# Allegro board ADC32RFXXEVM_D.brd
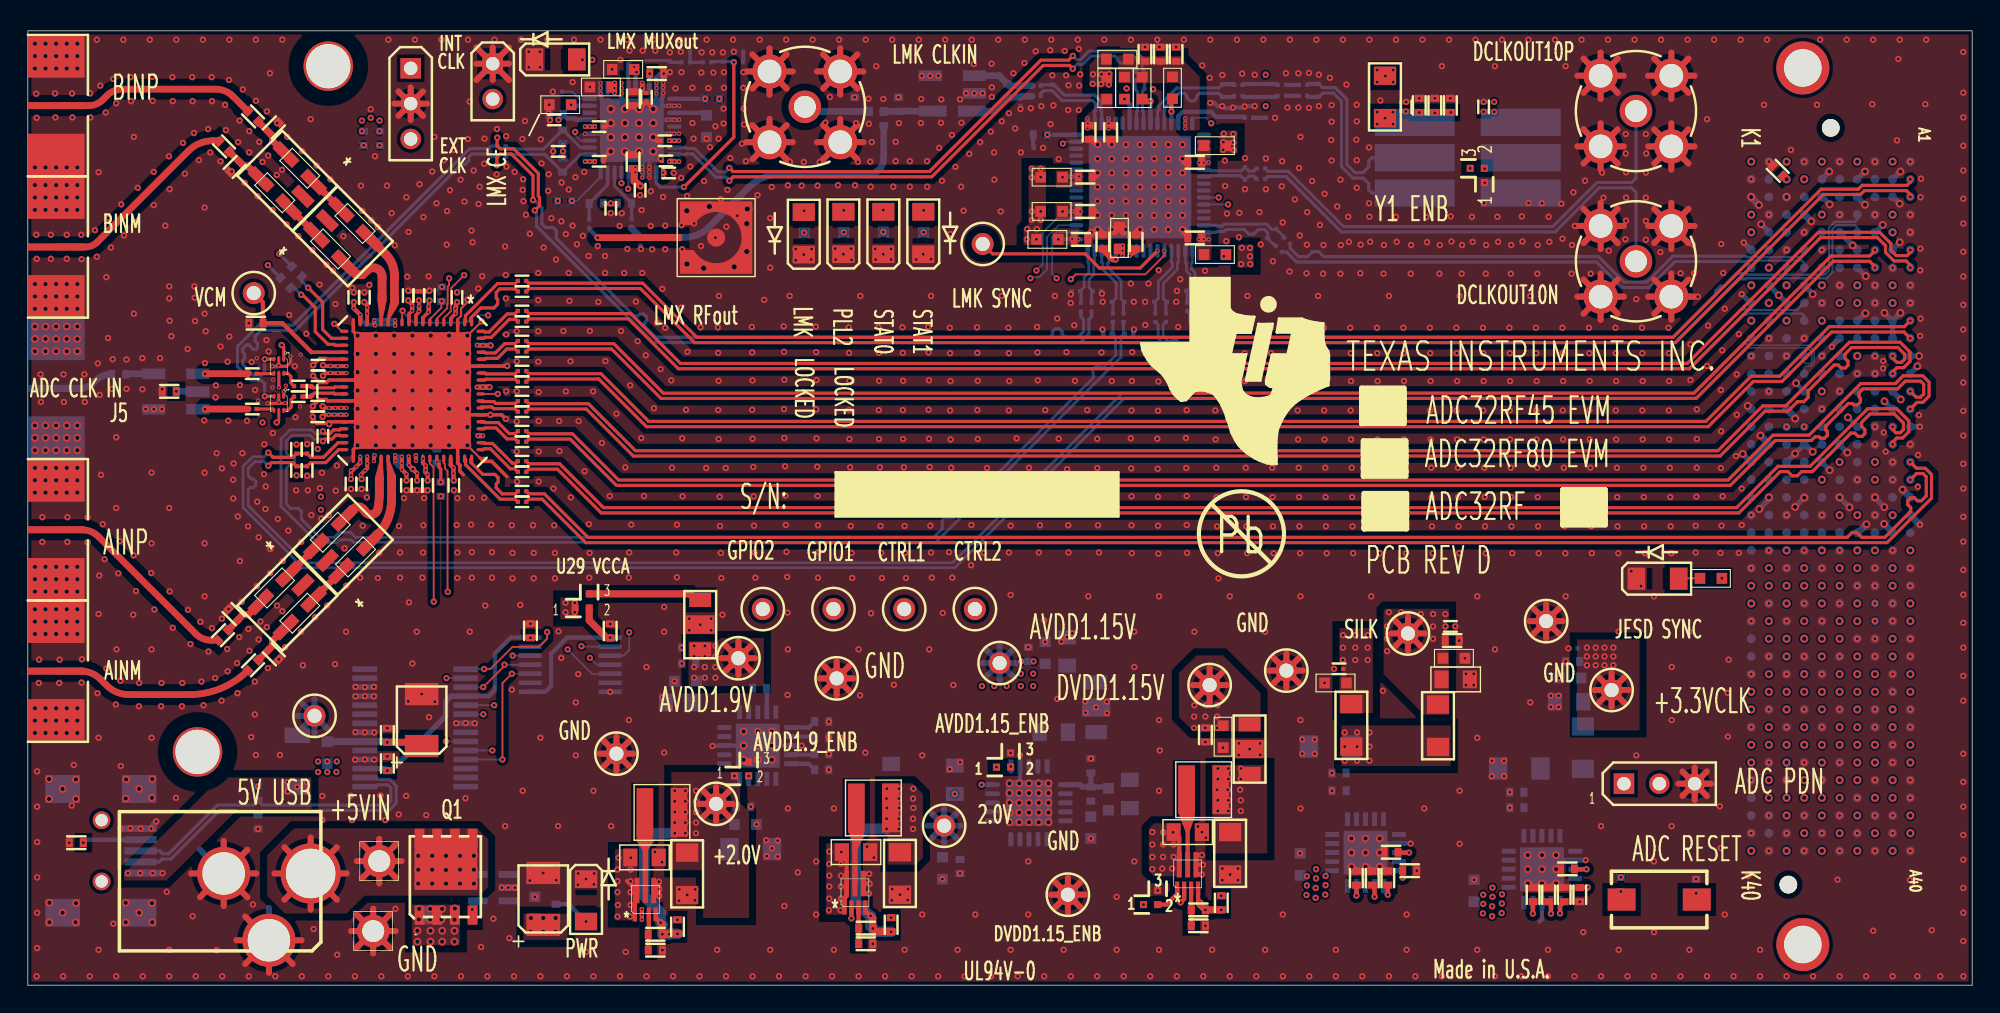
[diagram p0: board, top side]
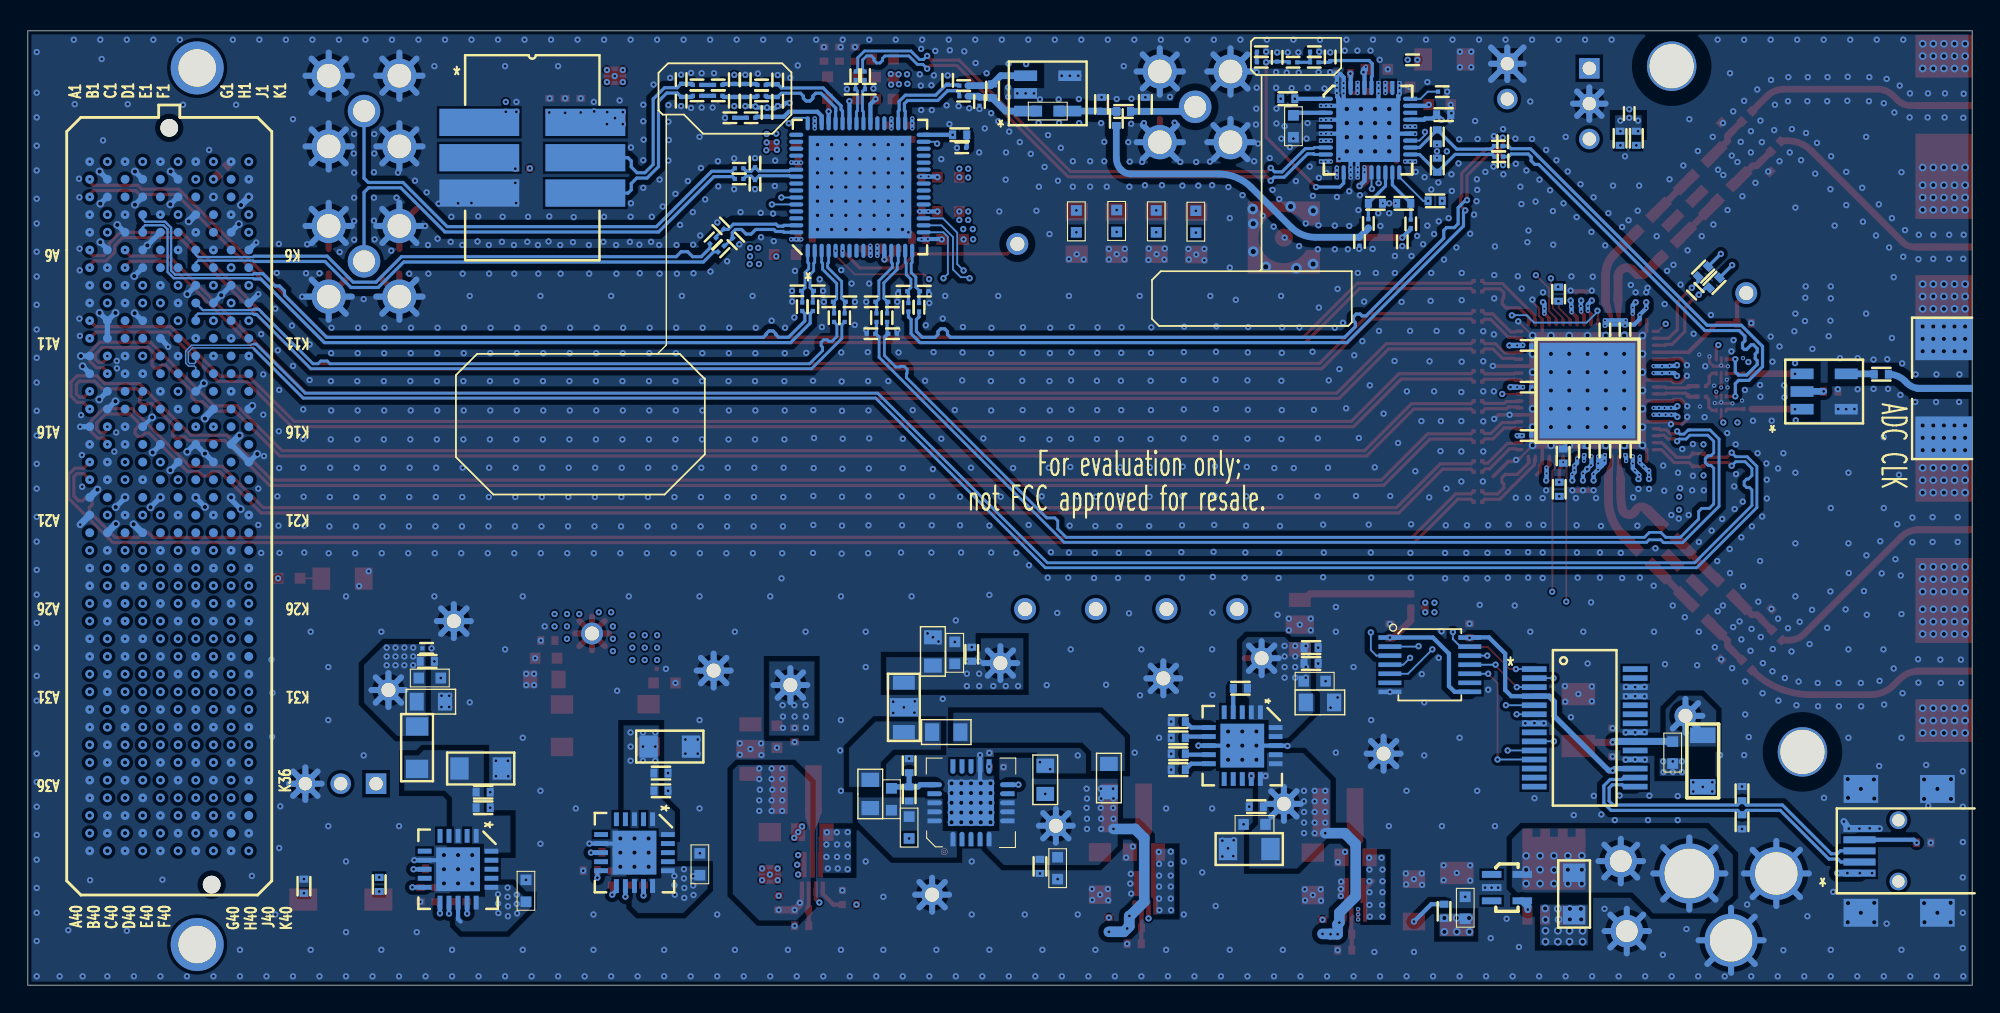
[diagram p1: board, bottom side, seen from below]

Outline 139.7 x 68.58 mm; copper layers: TOP, L2_GND, L3_PWR, L4_SIG, L5_GND, L6_PWR, L7_GND, BOTTOM. Coordinates in mm from the lower left corner of the outline.
Outline path: 0,68.58 0,0 139.7,0 139.7,68.58 0,68.58

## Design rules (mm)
net group CLK: nets CLKM CLKP
net group CLK_LAO: nets CLK_LAO_0M CLK_LAO_0P
net group CLKIN1: nets CLKIN1_N CLKIN1_P
net group DA0: nets DA0M DA0P
net group DA1: nets DA1M DA1P
net group DA2: nets DA2M DA2P
net group DA3: nets DA3M DA3P
net group DB0: nets DB0M DB0P
net group DB1: nets DB1M DB1P
net group DB2: nets DB2M DB2P
net group DB3: nets DB3M DB3P
net group DIFFPAIR9: nets GTXCLKM GTXCLKP
net group DP1: nets N19886018 N19886020
net group DP2: nets CLKLA_0M CLKLA_0P
net group DP3: nets N20235277 N20235286
net group DP4: nets N20015888 N20015984
net group DP5: nets SYSREF+ SYSREF-
net group DP6: nets AINM AINP
net group DP7: nets BINM BINP
net group DP8: nets LMX_OSCM LMX_OSCP
net group DP9: nets DA0_M DA0_P
net group DP10: nets DA1_M DA1_P
net group DP11: nets DA2_M DA2_P
net group DP12: nets DA3_M DA3_P
net group DP13: nets DB0_M DB0_P
net group DP14: nets DB1_M DB1_P
net group DP15: nets DB2_M DB2_P
net group DP16: nets DB3_M DB3_P
net group DP17: nets JESD_SYSREFM JESD_SYSREFP
net group DP18: nets N19879103 N19879149
net group DP19: nets LMX_CLKM LMX_CLKP
net group FPGA_JESD_CLK: nets FPGA_JESD_CLKM FPGA_JESD_CLKP
net group FPGA_JESD_SYSREF: nets FPGA_JESD_SYSREFM FPGA_JESD_SYSREFP
net group OSC: nets OSCN OSCP
net group OSCIN: nets OSCINN OSCINP
net group OSCOUT: nets OSCOUTN OSCOUTP
net group SYNCB: nets SYNCBM SYNCBP
net group SYSREF: nets SYSREFM SYSREFP
net group Y2: nets Y2_N Y2_P

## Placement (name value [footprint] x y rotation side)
C1  .1uF  [0603]  21.73 32.55 45 top
C6  .1uF  [0603]  23.55 30.77 45 top
C7  .1uF  [0603]  23.51 54.74 315 top
C8  .1uF  [0201]  76.43 48.72 270 bottom
C9  .1uF  [0201]  75.67 48.72 270 bottom
C12  .1uF  [0603]  21.75 52.9 315 top
C13  .1uF  [0201]  35.51 41.21 0 top
C14  .1uF  [0201]  35.51 41.97 0 top
C15  .1uF  [0201]  35.51 39.05 0 top
C16  .1uF  [0201]  35.51 39.81 0 top
C17  .1uF  [0201]  35.51 36.89 0 top
C18  .1uF  [0201]  35.51 37.66 0 top
C19  .1uF  [0201]  35.51 34.73 0 top
C20  .1uF  [0201]  35.51 35.5 0 top
C21  .1uF  [0201]  35.51 44.13 0 top
C22  .1uF  [0201]  35.51 43.37 0 top
C23  .1uF  [0201]  35.51 46.29 0 top
C24  .1uF  [0201]  35.51 45.53 0 top
C26  .1uF  [0201]  35.51 48.45 0 top
C27  .1uF  [0201]  35.51 47.69 0 top
C28  .01uF  [0402]  6.53 43.9 0 bottom
C30  .1uF  [0201]  35.51 50.61 0 top
C31  .1uF  [0201]  35.51 49.85 0 top
C33  .1uF  [0402]  10.16 42.67 180 top
C37  .1uF  [0201]  28.09 49.56 90 top
C38  .1uF  [0201]  26.39 47.09 270 bottom
C39  .1uF  [0201]  24.94 47.12 270 bottom
C40  .1uF  [0201]  23.42 49.43 90 top
C41  .1uF  [0201]  20.85 43.79 180 top
C42  .1uF  [0201]  20.83 41.61 180 top
C43  .1uF  [0201]  23.22 36.02 270 top
C44  .1uF  [0201]  24.92 38.38 90 bottom
C45  .1uF  [0201]  26.39 38.38 90 bottom
C46  .1uF  [0201]  27.2 35.92 270 top
C47  .1uF  [0201]  27.86 38.38 90 bottom
C48  .1uF  [0201]  27.33 49.56 90 top
C49  .1uF  [0201]  24.18 49.43 90 top
C50  .01uF  [0201]  20.85 44.55 180 top
C51  .01uF  [0201]  20.83 40.84 180 top
C52  .1uF  [0201]  23.98 36.02 270 top
C53  .1uF  [0201]  27.97 35.92 270 top
C54  .1uF  [0201]  30.84 49.43 90 top
C55  .1uF  [0201]  28.85 49.56 90 top
C56  .1uF  [0201]  28.73 35.92 270 top
C57  .1uF  [0201]  30.61 35.92 270 top
C58  .1uF  [0201]  31.98 39.5 180 bottom
C59  .1uF  [0201]  31.98 42.98 180 bottom
C60  .1uF  [0201]  31.98 45.97 180 bottom
C61  .1uF  [0402]  16.38 47.57 180 top
C67  .1uF  [0201]  84.06 48.75 270 bottom
C68  .1uF  [0201]  104.6 63.12 90 top
C69  .1uF  [0201]  83.3 48.75 270 bottom
C70  .68uF  [0402]  72.75 61.11 180 bottom
C71  3900pF  [0201]  87.73 62.33 0 bottom
C72  47pF  [0201]  86.59 62.71 90 bottom
C73  .01uF  [0201]  72.47 63.88 0 bottom
C74  .01uF  [0201]  72.47 64.64 0 bottom
C75  .1uF  [0201]  73.61 65.02 270 bottom
C77  .1uF  [0201]  99.03 63.12 270 top
C78  100pF  [0402]  99.97 63.22 270 top
C79  2200pF  [0402]  101.09 63.22 270 top
C80  10pF  [0402]  102.21 63.22 270 top
C81  .1uF  [0201]  90.09 64.69 180 bottom
C82  .1uF  [0201]  86.98 64.69 180 bottom
C83  .1uF  [0201]  85.82 65.05 270 bottom
C84  .1uF  [0201]  90.09 63.91 180 bottom
C85  .1uF  [0201]  86.98 63.9 180 bottom
C86  12pF  [0201]  85.82 63.52 90 bottom
C87  1uF  [0402]  76.25 61.29 90 top
C88  .1uF  [0402]  79.63 53.42 270 top
C89  0.01uF  [0402]  77.8 61.29 90 top
C90  1uF  [0402]  75.67 53.59 180 top
C91  1uF  [0402]  75.97 55.6 180 top
C92  1uF  [0402]  75.97 58.06 180 top
C93  1uF  [0402]  80.26 66.9 270 top
C94  .1uF  [0402]  81.38 66.9 270 top
C95  0.01uF  [0402]  82.5 66.9 270 top
C96  .1uF  [0402]  77.24 53.42 90 top
C97  10uF  [0603]  78.44 53.7 90 top
C98  1uF  [0402]  83.85 59.13 0 top
C99  1uF  [0402]  83.85 53.7 0 top
C101  4.7uF  [TANT_B]  28.3 19.05 90 top
C102  .1uF  [0402]  25.83 17.96 90 top
C103  47pF  [0402]  16.54 11.73 270 bottom
C104  47pF  [0402]  16.54 13.77 90 bottom
C105  .1uF  [0402]  25.83 15.93 90 top
C121  10uF  [0805]  59.51 9.56 0 top
C122  1uF  [0402]  66.98 8.53 270 bottom
C126  2.2uF  [0603]  65.71 8.41 270 bottom
C156  10uF  [0603]  103.91 6.78 90 bottom
C157  .1uF  [0402]  106.98 12.75 180 bottom
C158  1uF  [0402]  106.98 13.87 180 bottom
C159  47uF  [1206]  107.16 15.57 180 bottom
C160  33uF  [0805]  110.74 20.37 180 bottom
C161  10uF  [0603]  110.82 22.07 180 bottom
C162  .01uF  [0201]  111.05 24.21 180 bottom
C163  .1uF  [0402]  111 23.27 180 bottom
C166  1uF  [0402]  108.15 6.5 90 top
C170  .1uF  [0201]  88.6 58.7 0 bottom
C171  .1uF  [0201]  88.6 57.94 0 bottom
C172  47uF  [TANT_B]  37.03 6.2 90 top
C173  10uF  [0603]  36.42 5.56 90 bottom
C183  10uF  [0805]  44.31 9.18 0 top
C184  22uF  [1206]  47.37 8 270 top
C185  33uF  [0805]  46.86 20.32 180 bottom
C186  10uF  [0603]  47.24 21.84 180 bottom
C187  1uF  [0402]  47.5 23.11 180 bottom
C188  .1uF  [0402]  47.5 24.26 180 bottom
C189  47uF  [1206]  51.94 9.78 0 bottom
C190  10uF  [0603]  51.56 11.56 0 bottom
C191  1uF  [0402]  51.44 12.83 0 bottom
C193  .47uF  [0603]  77.65 13.36 90 bottom
C194  33uF  [0805]  74.67 23.98 90 bottom
C195  10uF  [0603]  73.1 23.88 90 bottom
C196  1uF  [0402]  71.88 23.78 90 bottom
C197  10uF  [0603]  76.38 11.33 270 bottom
C198  4.7uF  [0805]  66.6 14.76 90 bottom
C203  10uF  [0805]  83.34 11 0 top
C204  22uF  [1206]  86.39 9.47 270 top
C368  .1uF  [0402]  41.84 25.45 90 top
C369  .1uF  [0402]  36.11 25.47 270 top
C372  .1uF  [0201]  16.13 43.94 0 top
C373  .1uF  [0201]  16.13 41.4 0 top
C376  22uF  [1206]  62.66 8.03 270 top
C377  10uF  [0603]  85.88 17.86 270 top
C378  1uF  [0402]  84.61 17.98 270 top
C379  10uF  [0603]  93.95 21.72 180 top
C380  .01uF  [0201]  94.21 22.73 180 top
C381  10uF  [0603]  102.46 23.5 0 top
C382  .1uF  [0402]  102.34 24.77 0 top
C383  .01uF  [0201]  102.21 25.78 0 top
C384  33uF  [0805]  102.59 21.97 0 top
C385  47uF  [1206]  93.57 17.14 180 bottom
C386  10uF  [0603]  91.41 8.69 90 bottom
C387  1uF  [0402]  95.45 7.7 90 top
C388  .1uF  [0402]  94.21 13.97 180 bottom
C389  1uF  [0402]  94.21 15.24 180 bottom
C390  .1uF  [0201]  41.05 61.7 180 top
C391  .1uF  [0201]  45.85 59.23 0 top
C392  .1uF  [0201]  45.77 60.68 180 top
C393  .1uF  [0201]  46.05 58.37 0 top
C394  .047uF  [0201]  51.08 66.32 0 bottom
C395  560pF  [0201]  49.94 66.67 90 bottom
C396  .1uF  [0201]  43.99 57.12 270 top
C397  .1uF  [0201]  41.05 59.21 0 top
C398  1uF  [0402]  43.48 59.18 270 top
C399  .1uF  [0201]  37.82 62.18 180 top
C400  1uF  [0402]  37.97 62.56 0 bottom
C401  .1uF  [0201]  44.45 63.8 270 top
C402  1uF  [0402]  43.51 63.7 90 top
C403  10uF  [0603]  48.77 61.72 90 bottom
C404  1uF  [0402]  45.19 65.51 180 top
C405  10uF  [0603]  38.25 63.27 0 top
C406  10uF  [0603]  42.77 65.81 0 top
C407  10uF  [0603]  41.17 64.54 0 top
C408  100pF  [0201]  38.1 59.92 180 top
C409  100pF  [0201]  34.04 60.3 180 bottom
C410  100pF  [0201]  34.01 59.54 180 bottom
C411  100pF  [0201]  41.88 55.83 270 top
C412  100pF  [0201]  43.38 54.74 270 bottom
C413  100pF  [0201]  40.34 54.71 270 bottom
C414  .1uF  [0402]  14.02 25.15 45 top
C415  .1uF  [0402]  16.18 22.99 45 top
C416  .1uF  [0402]  16.18 62.43 315 top
C417  .1uF  [0402]  14.1 60.27 315 top
C418  .1uF  [0201]  79.58 65.35 90 bottom
C419  .1uF  [0201]  80.21 65.35 90 bottom
C420  6800pF  [0201]  47.27 67.08 180 bottom
C421  6800pF  [0201]  46.13 66.7 90 bottom
C424  .1uF  [0402]  14.78 26.67 315 top
C425  .1uF  [0402]  17.68 23.77 135 top
C426  .1uF  [0402]  17.68 61.65 225 top
C427  .1uF  [0402]  14.86 58.8 45 top
C428  .1uF  [0201]  24.64 62.64 90 bottom
C429  .1uF  [0201]  19.43 43.05 0 top
C430  .1uF  [0201]  19.43 42.29 0 top
C431  .1uF  [0201]  33.73 60.6 90 bottom
C432  .1uF  [0201]  33.71 59.23 270 bottom
D1  LED GREEN  [LED_1206]  61.47 54.05 270 top
D2  LED GREEN  [LED_1206]  64.34 54.05 270 top
D3  LED GREEN  [LED_1206]  55.75 54.03 270 top
D4  LED GREEN  [LED_1206]  58.6 54.05 270 top
D5  LED GREEN  [LED_1206]  117.09 29.21 180 top
D6  LED GREEN  [LED_1206]  40.11 6.1 90 top
D7  LED GREEN  [LED_1206]  37.92 66.52 180 top
F1  FUSE 10A 63V FAST  [1206]  28.6 6.55 270 bottom
FB1  120 OHM @ 100MHz  [1206]  97.51 63.83 90 top
FB2  120  [0603]  77.52 64.47 270 top
FB3  120  [0603]  73.25 53.59 0 top
FB4  120  [0603]  73.56 55.6 0 top
FB5  120  [0603]  73.56 58.06 0 top
FB6  120  [0603]  78.28 66.55 0 top
FB7  120  [0603]  78.79 64.47 270 top
FB8  120  [0603]  80.06 64.47 270 top
FB9  120  [0603]  82.25 64.49 270 top
FB10  120  [0603]  85.29 60.33 180 top
FB11  120  [0603]  85.29 52.5 180 top
FB12  1K OHM @ 100MHz  [1806]  19.35 16.1 270 bottom
FB16  120 OHM @ 100MHz  [1206]  111.73 17.07 90 bottom
FB17  27uF  [1206_BEAD_NFM31P]  76.76 19.96 90 bottom
FB19  27uF  [1206_BEAD_NFM31P]  87.78 16.97 90 top
FB20  27uF  [1206_BEAD_NFM31P]  48.31 25.91 90 top
FB21  120 OHM @ 100MHz  [1206]  95.1 18.67 90 top
FB22  120 OHM @ 100MHz  [1206]  101.32 18.64 90 top
HS1  COPPER PIN FIN HEAT SINK  [HEATSINK_270X270]  27.64 42.72 180 bottom
J1  SMA, JACK, END LAUNCH  [SMA_SMEL_DUAL_PSF-S01_250X215]  0 32.73 90 top
J2  SMA, JACK, END LAUNCH  [SMA_SMEL_DUAL_PSF-S01_250X215]  0 22.57 90 top
J3  SMA, JACK, END LAUNCH  [SMA_SMEL_DUAL_PSF-S01_250X215]  0 63.21 90 top
J4  SMA, JACK, END LAUNCH  [SMA_SMEL_DUAL_PSF-S01_250X215]  0 53.05 90 top
J5  CONN, SMA, JACK, 50 OHM, EDGE MNT  [SMA_SMEL_DUAL_PSF-S01_250X215]  0 42.89 270 bottom
J7  SMA_THVT_REC  [SMA_THVT_312X312]  55.83 63.12 0 top
J10  CON, SMVT, HS, FIELD ARRAY, 400POS, MALE  [CON_SMVT_40X10_SEAM_MTG]  129.54 34.42 90 bottom
J11  CONN, USB MINI AB, SMT  [CON_SMRT_USBMNE20_F]  4.65 9.65 0 bottom
J13  SMA_THVT_REC  [SMA_THVT_312X312]  115.54 62.81 0 top
J14  SMA_THVT_REC  [SMA_THVT_312X312]  115.54 52.02 0 top
J15  CONN, JACK, PWR, MINI, R/A, TH  [CON_RAPC722_JACK_THVT_3]  17.2 8.03 270 top
J16  SMP_PCB_SMT  [SMP_B120]  49.45 53.72 270 top
JP1  HDR, THVT, 3POS  [HDR_THVT_1X3_100_M]  114.68 14.48 90 top
JP2  HEADER_1x2_100_430L  [HDR_THVT_1X2_100_M]  33.4 66.22 0 top
JP3  HDR, THVT, 3POS  [HDR_THVT_1X3_100_M]  27.51 65.89 0 top
L1  .47uH  [IND_SM_XFL4015]  45.56 12.41 0 top
L2  .47uH  [IND_SM_XFL4015]  60.75 12.74 0 top
L3  .47uH  [IND_SM_XFL4015]  84.48 14.05 0 top
MT1  STANDOFF, FEMALE, 4-40 X 1 3/16", AL  [MFG125_PLATED]  21.59 66.04 0 top
MT2  STANDOFF, FEMALE, 4-40 X 1 3/16", AL  [MFG125_PLATED]  12.19 16.76 0 top
NOREF  -  []  98.35 -28.6 0 top
NOREF#2  -  []  0 68.58 0 top
NOREF#3  -  []  480.29 162.18 0 top
NOREF#4  -  []  -3.84 37.72 0 top
NOREF#5  -  []  227.97 11.43 0 top
NOREF#6  -  []  12.7 0 90 top
NOREF#7  -  []  86.59 -25.65 0 top
NOREF#8  -  []  85.17 31.17 0 top
NOREF#9  -  []  -109.98 325.27 0 top
NOREF#10  -  []  -120.68 -149.22 0 top
NOREF#11  -  []  712.19 113.13 0 top
NOREF#12  -  []  101.9 3.91 0 top
NOREF#13  -  []  130.94 -11.73 0 top
NOREF#14  -  []  85.72 -4.45 180 bottom
Q1  CSD18532Q5  [SON_Q5B_8]  30.05 7.8 90 top
R1  0  [0603]  17.73 28.54 45 top
R11  0  [0603]  19.54 26.73 45 top
R13  0  [0603]  19.54 58.71 315 top
R23  0  [0603]  17.74 56.95 315 top
R26  100  [0201]  20.42 42.68 90 top
R29  100  [0201]  21.2 39.44 90 top
R31  0  [0402]  29.67 35.64 90 bottom
R32  10K  [0402]  29.39 38.02 90 bottom
R33  1K  [0402]  114.45 7.24 270 bottom
R34  1K  [0402]  29.72 49.66 270 bottom
R35  10K  [0402]  119.86 7.11 90 bottom
R40  100  [0201]  19.89 49.86 45 bottom
R47  39K  [0201]  72.59 60.17 0 bottom
R48  0  [0201]  81.77 47.97 270 bottom
R49  0  [0201]  81.01 47.97 270 bottom
R50  240  [0201]  80.63 49.11 180 bottom
R51  240  [0201]  82.15 49.11 0 bottom
R52  240  [0201]  82.92 49.9 180 bottom
R53  240  [0201]  84.44 49.9 0 bottom
R54  620  [0201]  89.26 62.33 0 bottom
R55  49.9  [0201]  71.32 63.5 270 bottom
R56  0  [0603]  66.42 62.81 0 bottom
R57  18  [0402]  60.98 62.79 0 bottom
R58  292  [0402]  59.4 63.29 90 bottom
R59  292  [0402]  62.55 63.29 90 bottom
R60  100  [0402]  70.38 64.26 90 bottom
R63  120  [0201]  76.82 49.87 0 bottom
R64  120  [0201]  75.3 49.87 180 bottom
R65  100  [0201]  78.73 47.97 270 bottom
R66  100  [0201]  77.96 47.97 270 bottom
R67  200  [0201]  79.11 49.11 0 bottom
R68  200  [0201]  77.58 49.11 180 bottom
R69  100  [0201]  77.57 46.81 180 bottom
R70  100  [0201]  79.12 46.81 0 bottom
R71  130  [0201]  88.94 65.07 270 bottom
R72  100  [0201]  91.62 64.69 180 bottom
R73  82  [0201]  92.76 65.07 90 bottom
R74  49.9  [0201]  88.15 65.07 90 bottom
R75  0  [0201]  90.47 53.49 315 bottom
R76  130  [0201]  88.94 63.52 90 bottom
R77  240  [0201]  89.91 54.56 45 bottom
R78  240  [0201]  88.83 53.48 225 bottom
R79  0  [0201]  89.89 52.91 315 bottom
R80  100  [0201]  91.62 63.91 180 bottom
R81  82  [0201]  92.76 63.53 270 bottom
R82  49.9  [0201]  88.15 63.52 270 bottom
R84  750  [0603]  61.47 54.91 270 bottom
R85  750  [0603]  64.36 54.89 270 bottom
R86  750  [0603]  55.78 54.86 270 bottom
R87  750  [0603]  58.62 54.89 270 bottom
R88  750  [0603]  120.93 29.24 0 top
R89  0  [0402]  125.73 58.52 135 top
R95  0  [0603]  21.51 16.71 90 bottom
R96  0  [0402]  3.48 10.24 0 top
R124  0  [0402]  109.27 6.5 270 top
R125  0  [0402]  110.39 6.5 270 top
R126  0  [0402]  111.51 6.5 90 top
R127  0  [0402]  110.62 8.36 0 top
R132  287K  [0402]  45.09 3.66 180 top
R133  1K  [0402]  37.95 5.31 90 bottom
R134  162K  [0402]  45.09 2.51 0 top
R136  1M  [0402]  46.68 4.19 90 top
R137  36.5K  [0402]  52.58 21.34 0 bottom
R138  0  [0402]  57.04 18.94 180 bottom
R139  0  [0402]  57.04 17.77 180 bottom
R140  0  [0402]  57.04 16.63 180 bottom
R141  0  [0402]  57.04 15.49 180 bottom
R143  2.4K  [0402]  76.38 13.74 90 bottom
R145  4.75K  [0402]  76.38 15.77 90 bottom
R146  82K  [0402]  84.1 5.41 180 top
R147  162K  [0402]  84.1 4.27 0 top
R148  1M  [0402]  85.75 5.92 90 top
R151  240  [0201]  87.45 57.56 270 bottom
R152  240  [0201]  87.45 59.08 90 bottom
R153  1M  [0402]  62.03 4.34 90 top
R154  124K  [0402]  60.21 4.1 180 top
R155  162K  [0402]  60.21 2.97 0 top
R157  0  [0805]  62.03 14.88 270 bottom
R158  0  [0805]  79.17 13.74 270 bottom
R159  0  [0805]  73.71 18.19 180 bottom
R164  0  [0402]  18.52 50.47 315 bottom
R165  0  [0402]  19.33 51.28 315 bottom
R166  182  [0201]  19.3 36.98 90 top
R167  182  [0201]  19.3 38.51 270 top
R168  68  [0201]  20.07 36.98 270 top
R169  68  [0201]  20.07 38.51 90 top
R170  0  [0402]  96.6 7.7 270 top
R171  0  [0402]  97.94 9.55 0 top
R172  0  [0402]  97.71 7.7 270 top
R173  0  [0402]  99.29 8.23 180 top
R174  150  [0201]  51.08 67.08 180 bottom
R175  49.9  [0402]  38.43 60.96 270 bottom
R176  49.9  [0402]  38.43 58.93 90 bottom
R177  49.9  [0402]  42.88 56.18 180 bottom
R178  49.9  [0402]  40.84 56.18 0 bottom
R179  680  [0201]  38.07 64.21 0 bottom
R180  240  [0201]  80.54 64.39 0 bottom
R181  240  [0201]  79.25 64.39 180 bottom
R182  0  [0201]  48.79 66.32 180 bottom
R183  12  [0201]  47.27 66.32 180 bottom
R184  0  [0402]  38.58 56.36 180 bottom
R185  680  [0201]  40.21 66.5 0 bottom
R186  12k  [0402]  49.17 63.7 0 bottom
R187  49.9  [0201]  40.94 53.42 90 bottom
R188  10K  [0402]  24.13 60.86 270 bottom
R189  10K  [0402]  25.3 60.86 270 bottom
R191  0  [0402]  61.49 62.28 270 bottom
R192  49.9  [0201]  44.02 53.44 90 bottom
SJP1  SOLDER JUMPER, 0402  [SMD_JUMPER_L_0402]  104.65 58.19 90 top
SJP2  SOLDER JUMPER, 0402  [SMD_JUMPER_L_0402]  51.28 15.04 0 top
SJP3  SOLDER JUMPER, 0402  [SMD_JUMPER_L_0402]  70.1 15.67 0 top
SJP4  SOLDER JUMPER, 0402  [SMD_JUMPER_L_0402]  80.67 5.79 0 top
SJP5  SOLDER JUMPER, 0402  [SMD_JUMPER_L_0402]  39.83 27.1 0 top
SW1  SWITCH, SMT, PUSHBUTTON  [SW_SMVT_SPST_EVQPJX_2]  117.21 6.15 0 top
T1  ETC1-1-13  [TFMR_5_150X150_50]  18.64 27.63 45 top
T2  ETC1-1-13  [TFMR_5_150X150_50]  22.63 31.65 225 top
T3  ETC1-1-13  [TFMR_5_150X150_50]  18.64 57.81 315 top
T4  ETC1-1-13  [TFMR_5_150X150_50]  22.63 53.82 135 top
T5  ETC1-1-13  [TFMR_5_150X150_50]  10.63 42.66 0 bottom
T6  TC1-1-13M+  [TFMR_5_150X150_50]  66.42 64.08 0 bottom
TP2  RED  [TP_THVT_060_RND]  16.23 49.73 0 top
TP3  YELLOW  [TP_THVT_060_RND]  57.89 27.03 0 top
TP4  RED  [TP_THVT_060_RND]  20.6 19.35 0 top
TP7  YELLOW  [TP_THVT_060_RND]  52.81 27.03 0 top
TP12  RED  [TP_THVT_060_RND]  113.79 21.21 0 top
TP17  Testloop_Red  [TESTPOINT_62DIA]  25.25 8.92 0 top
TP18  Testloop_Black  [TESTPOINT_62DIA]  24.82 3.89 0 top
TP19  BLK  [TP_THVT_060_RND]  109.09 26.16 0 top
TP20  RED  [TP_THVT_060_RND]  51.05 23.5 0 top
TP21  BLK  [TP_THVT_060_RND]  58.12 22.05 0 top
TP22  RED  [TP_THVT_060_RND]  69.82 23.14 90 top
TP25  YELLOW  [TP_THVT_060_RND]  68.61 53.26 0 top
TP26  RED  [TP_THVT_060_RND]  49.45 13.03 0 top
TP27  BLK  [TP_THVT_060_RND]  42.29 16.64 0 top
TP28  RED  [TP_THVT_060_RND]  65.84 11.46 0 top
TP29  BLK  [TP_THVT_060_RND]  74.73 6.5 0 top
TP30  RED  [TP_THVT_060_RND]  84.91 21.56 0 top
TP31  BLK  [TP_THVT_060_RND]  90.42 22.61 0 top
TP32  YELLOW  [TP_THVT_060_RND]  62.97 27.03 0 top
TP33  YELLOW  [TP_THVT_060_RND]  68.05 27.03 0 top
TP34  RED  [TP_THVT_060_RND]  99.16 25.27 0 top
U1  ADC32RF4X_72QFN  [QFN_72_10MMX10MM_0P50MM_PWRPAD]  27.64 42.74 270 top
U3  LMK04828  [QFN_64_360X360_0P50MM_PWRPAD]  79.91 57.35 90 bottom
U5  FT245RL  [SSOP_28_413X220_26]  27.84 18.49 180 bottom
U11  TPS62085  [QFN_RLT_7]  59.43 6.64 90 top
U12  TPS7A4700  [QFN_20_199X199_0P65MM]  108.79 8.33 270 bottom
U14  TPS62085  [QFN_RLT_7]  44.37 6.14 90 top
U15  TPS2400  [DBV5]  33.43 7.01 180 bottom
U16  TPS7A7200  [QFN_20_199X199_0P65MM]  52.44 17.21 270 bottom
U17  TPS74201/QFN20  [QFN20_RGW_P65PITCH]  71.93 13.11 90 bottom
U18  TPS62085  [QFN_RLT_7]  83.33 8 90 top
U29  TXB0104  [TSSOP14]  38.97 23.03 180 bottom
U30  LMX2582_LM2592  [QFN40_RTA_RTB_RHA]  43.41 61.44 180 bottom
U31  TPS7A4700  [QFN_20_199X199_0P65MM]  96.11 9.53 270 bottom
U32  MASW_009444  [PDFN_6_P35MM]  18.03 44.48 270 top
U33  MASW_009444  [PDFN_6_P35MM]  18.03 41.81 270 top
Y1  122.88MHz  [VCXO_6_CUSTOM]  103.45 59.46 180 bottom

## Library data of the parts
C1 C6 C7 C12 C414-C417 C424-C427 = CAP_0603_0.1uF_H: tolerance: 10%
C8 C9 C67 C69 C83 C87-C96 C98 C99 C170 C171 C368 C369 C390-C393 C396 C397 C399 C401 C418 C419 = CAPACITOR_NP_1: tolerance: 10%
C13-C24 C26 C27 C30 C31 = CAP_0201_0.1uF: tolerance: 10%
C28 C72 = CAP NP_0: tolerance: 5%
C33 C157 C163 C188 C382 C388 = CAP0603: tolerance: 10%
C37-C49 C52-C61 C372 C373 C428-C432 = CAP0402_0: tolerance: 10%
C50 C51 = CAP0402_0: tolerance: +/-10%
C68 C70 C71 C82 C85 C102 C105 C122 C158 C166 C191 C387 C389 C394 C395 C398 C400 C402 C404 C420 C421 = CAP NP_0: tolerance: 10%
C73 C74 = CAP_0402_0.01uF_H: tolerance: 10%
C75 = CAP_0402_0.1uF: tolerance: 10%
C77 C81 C84 = CAP_0402_0.1uF_H: tolerance: 10%
C78 C408-C413 = CAP_0603_100pF_H
C79 = CAP_0402_2200pF_H
C80 = CAP_0402_10pF_H
C86 = CAPACITOR_NP_1: tolerance: 2%
C97 = CAP NP_2: tolerance: 10%
C101 = CAP_TANT_B_4.7uF_10V
C103 C104 = CAP0603: tolerance: 1%
C121 C156 C173 C183 C187 C190 C196 C197 C203 C378 C386 C403 C405-C407 = CAP NP_1: tolerance: 10%
C126 = CAP_0603_2.2uF
C159 C189 C385 = CAP NP_0: tolerance: 20%
C160 C185 C186 C194 C195 C377 C384 = CAP0201: tolerance: 20%
C161 C379 C381 = CAP0201: tolerance: 10%
C162 C380 C383 = CAP0402_0: tolerance: 10V
C172 = CAP POL-B: tolerance: 10%
C184 C204 C376 = CAP: tolerance: 10%
C193 C198 = CAP_0603_.47uF
D1-D5 D7 = LED
D6 = LED_GREEN_1206
F1 = FUSE_0
FB1-FB12 FB16 FB21 FB22 = FERRITE_BEAD_0402_H
FB17 FB19 FB20 = BEAD_NFM31P
HS1 = HEATSINK_270x270
J1-J5 = SMA-END_PLUG_ROUND
J7 J13 J14 = SMA-THVT_142-0701-201_REC
J10 = CON_SMVT_40X10_ASP-134487-01
J11 = USB_MINI_AB_MNE20-5G5P10
J15 = CONN JACK PWR
J16 = SMP_PLUG_SMT
JP1 JP3 SJP1-SJP5 = SMD_JUMPER_1x3
JP2 = HDR_2x1_100
L1-L3 = CHOKE
MT1 MT2 = MOUNTING_HOLE
Q1 = CSD18532Q5B
R1 R11 R13 R23 = Res_0603_Zero_H_DNI
R26 R29 = Res_0201_200_H: tolerance: 1%
R31 = Res_0402_Zero_DNI
R32 R33 R35 R47 R54 R174 R188 R189 = R_1: tolerance: 1%
R34 = RES0603: tolerance: 1%
R40 = Res_0201_H: tolerance: 1%
R48 R49 R65 R66 R75 R79 R157-R159 R182 = Res_0402_Zero_H_DNI
R50-R53 R63 R64 R67 R68 R77 R78 R151 R152 R180 R181 = Res_0402_249
R55 R175-R179 R185 R187 R192 = Res_0402_49.9: tolerance: 1%
R56 R95 = Res_0603_Zero_DNI
R57 R183 R186 = Res_0402_18
R58 R59 = Res_0402_270
R60 R69 R70 = Res_0603_100
R71 R73 R74 R76 R81 R82 = RESISTOR_0: tolerance: 1%
R72 R80 = Res_0402_100_H
R84-R88 = RESISTOR_0
R89 = Res_0402_Zero
R96 R164 R165 R184 R191 = R
R124-R127 R138-R141 R170-R173 = R: tolerance: 5%
R132 R146 R154 = Res_0603_Zero_H
R133 = Res_0402_1k: tolerance: 1%
R134 R136 R147 R148 R153 R155 = R: tolerance: 1%
R137 = Res_0402_Zero_H
R143 = Res_0603_12.4k
R145 = Res_0603_10k
R166-R169 = Res_0402_49.9
SW1 = SPST_EVQ-PJ
T1-T5 = BALUN_ETC1-1-13
T6 = TFMR_5_TC1-1-13M+
TP2 TP4 = TESTPOINT_RED
TP3 TP7 TP12 TP20 TP22 TP25 TP32-TP34 = TESTPOINT_BLUE
TP17 TP18 = TESTLOOP_BLACK
TP19 TP21 TP27 TP29 TP31 = TESTPOINT_BLK
TP26 TP28 TP30 = TESTLOOP_RED
U1 = ADC32RF4X_72QFN
U3 = LMK04828
U5 = FT245RL
U11 U14 U18 = TPS62085/62086/62087
U12 U31 = TPS7A4700
U15 = TPS2400
U16 = TPS7A7300
U17 = TPS74201/QFN20
U29 = TXS0104E: Tolerance: ***; User Part Number: ***
U30 = LMX2582_LM2592
U32 U33 = RF_SWITCH_MASW_009444
Y1 = OSC_SM_6_TCO-2100-SERIES_2

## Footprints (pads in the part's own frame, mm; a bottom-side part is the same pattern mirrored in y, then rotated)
0201
  rect 0.305x0.305 smd: 1(-0.305,0) 2(0.305,0)
0402
  rect 0.508x0.635 smd: 1(-0.508,0) 2(0.508,0)
0603
  rect 0.762x0.787 smd: 1(-0.787,0) 2(0.787,0)
0805
  rect 1.016x1.27 smd: 1(-1.016,0) 2(1.016,0)
1206
  rect 1.321x1.6 smd: 1(-1.524,0) 2(1.524,0)
1206_BEAD_NFM31P
  rect 1.016x1.575 smd: 1(-1.778,0) 3(1.778,0)
  rect 1.321x2.032 smd: 2(0,0)
1806
  rect 1.118x1.829 smd: 1(-1.854,0) 2(1.854,0)
CON_RAPC722_JACK_THVT_3
  round 4.318 hole 3.556: 1(0,3.124)
  round 3.81 hole 3.048: 2(0,-3.124) 3(4.801,0.127)
CON_SMRT_USBMNE20_F
  round 1.27 hole 0.889 unplated: (0.65,-2.2) (0.65,2.2)
  rect 2.311x0.508 smd: 1(3.45,1.6) 2(3.45,0.8) 3(3.45,0) 4(3.45,-0.8) 5(3.45,-1.6)
  rect 2.489x2.007 smd: 6(-2.15,-4.45) 7(3.35,-4.45) 8(3.35,4.45) 9(-2.15,4.45)
CON_SMVT_40X10_SEAM_MTG
  round 3.81 hole 2.692: (-31.496,-2.007) (31.496,-2.007)
  round 1.27 hole 1.27 unplated: (-27.191,-3.048) (27.191,0)
  round 0.635 smd: A1(24.765,5.715) A2(23.495,5.715) A3(22.225,5.715) A4(20.955,5.715) A5(19.685,5.715) A6(18.415,5.715) A7(17.145,5.715) A8(15.875,5.715) A9(14.605,5.715) A10(13.335,5.715) A11(12.065,5.715) A12(10.795,5.715) A13(9.525,5.715) A14(8.255,5.715) A15(6.985,5.715) A16(5.715,5.715) A17(4.445,5.715) A18(3.175,5.715) A19(1.905,5.715) A20(0.635,5.715) A21(-0.635,5.715) A22(-1.905,5.715) A23(-3.175,5.715) A24(-4.445,5.715) A25(-5.715,5.715) A26(-6.985,5.715) A27(-8.255,5.715) A28(-9.525,5.715) A29(-10.795,5.715) A30(-12.065,5.715) A31(-13.335,5.715) A32(-14.605,5.715) A33(-15.875,5.715) A34(-17.145,5.715) A35(-18.415,5.715) A36(-19.685,5.715) A37(-20.955,5.715) A38(-22.225,5.715) A39(-23.495,5.715) A40(-24.765,5.715) B1(24.765,4.445) B2(23.495,4.445) B3(22.225,4.445) B4(20.955,4.445) B5(19.685,4.445) B6(18.415,4.445) B7(17.145,4.445) B8(15.875,4.445) B9(14.605,4.445) B10(13.335,4.445) B11(12.065,4.445) B12(10.795,4.445) B13(9.525,4.445) B14(8.255,4.445) B15(6.985,4.445) B16(5.715,4.445) B17(4.445,4.445) B18(3.175,4.445) B19(1.905,4.445) B20(0.635,4.445) B21(-0.635,4.445) B22(-1.905,4.445) B23(-3.175,4.445) B24(-4.445,4.445) B25(-5.715,4.445) B26(-6.985,4.445) B27(-8.255,4.445) B28(-9.525,4.445) B29(-10.795,4.445) B30(-12.065,4.445) B31(-13.335,4.445) B32(-14.605,4.445) B33(-15.875,4.445) B34(-17.145,4.445) B35(-18.415,4.445) B36(-19.685,4.445) B37(-20.955,4.445) B38(-22.225,4.445) B39(-23.495,4.445) B40(-24.765,4.445) C1(24.765,3.175) C2(23.495,3.175) C3(22.225,3.175) C4(20.955,3.175) C5(19.685,3.175) C6(18.415,3.175) C7(17.145,3.175) C8(15.875,3.175) C9(14.605,3.175) C10(13.335,3.175) C11(12.065,3.175) C12(10.795,3.175) C13(9.525,3.175) C14(8.255,3.175) C15(6.985,3.175) C16(5.715,3.175) C17(4.445,3.175) C18(3.175,3.175) C19(1.905,3.175) C20(0.635,3.175) C21(-0.635,3.175) C22(-1.905,3.175) C23(-3.175,3.175) C24(-4.445,3.175) C25(-5.715,3.175) C26(-6.985,3.175) C27(-8.255,3.175) C28(-9.525,3.175) C29(-10.795,3.175) C30(-12.065,3.175) C31(-13.335,3.175) C32(-14.605,3.175) C33(-15.875,3.175) C34(-17.145,3.175) C35(-18.415,3.175) C36(-19.685,3.175) C37(-20.955,3.175) C38(-22.225,3.175) C39(-23.495,3.175) C40(-24.765,3.175) D1(24.765,1.905) D2(23.495,1.905) D3(22.225,1.905) D4(20.955,1.905) D5(19.685,1.905) D6(18.415,1.905) D7(17.145,1.905) D8(15.875,1.905) D9(14.605,1.905) D10(13.335,1.905) D11(12.065,1.905) D12(10.795,1.905) D13(9.525,1.905) D14(8.255,1.905) D15(6.985,1.905) D16(5.715,1.905) D17(4.445,1.905) D18(3.175,1.905) D19(1.905,1.905) D20(0.635,1.905) D21(-0.635,1.905) D22(-1.905,1.905) D23(-3.175,1.905) D24(-4.445,1.905) D25(-5.715,1.905) D26(-6.985,1.905) D27(-8.255,1.905) D28(-9.525,1.905) D29(-10.795,1.905) D30(-12.065,1.905) D31(-13.335,1.905) D32(-14.605,1.905) D33(-15.875,1.905) D34(-17.145,1.905) D35(-18.415,1.905) D36(-19.685,1.905) D37(-20.955,1.905) D38(-22.225,1.905) D39(-23.495,1.905) D40(-24.765,1.905) E1(24.765,0.635) E2(23.495,0.635) E3(22.225,0.635) E4(20.955,0.635) E5(19.685,0.635) E6(18.415,0.635) E7(17.145,0.635) E8(15.875,0.635) E9(14.605,0.635) E10(13.335,0.635) E11(12.065,0.635) E12(10.795,0.635) E13(9.525,0.635) E14(8.255,0.635) E15(6.985,0.635) E16(5.715,0.635) E17(4.445,0.635) E18(3.175,0.635) E19(1.905,0.635) E20(0.635,0.635) E21(-0.635,0.635) E22(-1.905,0.635) E23(-3.175,0.635) E24(-4.445,0.635) E25(-5.715,0.635) E26(-6.985,0.635) E27(-8.255,0.635) E28(-9.525,0.635) E29(-10.795,0.635) E30(-12.065,0.635) E31(-13.335,0.635) E32(-14.605,0.635) E33(-15.875,0.635) E34(-17.145,0.635) E35(-18.415,0.635) E36(-19.685,0.635) E37(-20.955,0.635) E38(-22.225,0.635) E39(-23.495,0.635) E40(-24.765,0.635) F1(24.765,-0.635) F2(23.495,-0.635) F3(22.225,-0.635) F4(20.955,-0.635) F5(19.685,-0.635) F6(18.415,-0.635) F7(17.145,-0.635) F8(15.875,-0.635) F9(14.605,-0.635) F10(13.335,-0.635) F11(12.065,-0.635) F12(10.795,-0.635) F13(9.525,-0.635) F14(8.255,-0.635) F15(6.985,-0.635) F16(5.715,-0.635) F17(4.445,-0.635) F18(3.175,-0.635) F19(1.905,-0.635) F20(0.635,-0.635) F21(-0.635,-0.635) F22(-1.905,-0.635) F23(-3.175,-0.635) F24(-4.445,-0.635) F25(-5.715,-0.635) F26(-6.985,-0.635) F27(-8.255,-0.635) F28(-9.525,-0.635) F29(-10.795,-0.635) F30(-12.065,-0.635) F31(-13.335,-0.635) F32(-14.605,-0.635) F33(-15.875,-0.635) F34(-17.145,-0.635) F35(-18.415,-0.635) F36(-19.685,-0.635) F37(-20.955,-0.635) F38(-22.225,-0.635) F39(-23.495,-0.635) F40(-24.765,-0.635) G1(24.765,-1.905) G2(23.495,-1.905) G3(22.225,-1.905) G4(20.955,-1.905) G5(19.685,-1.905) G6(18.415,-1.905) G7(17.145,-1.905) G8(15.875,-1.905) G9(14.605,-1.905) G10(13.335,-1.905) G11(12.065,-1.905) G12(10.795,-1.905) G13(9.525,-1.905) G14(8.255,-1.905) G15(6.985,-1.905) G16(5.715,-1.905) G17(4.445,-1.905) G18(3.175,-1.905) G19(1.905,-1.905) G20(0.635,-1.905) G21(-0.635,-1.905) G22(-1.905,-1.905) G23(-3.175,-1.905) G24(-4.445,-1.905) G25(-5.715,-1.905) G26(-6.985,-1.905) G27(-8.255,-1.905) G28(-9.525,-1.905) G29(-10.795,-1.905) G30(-12.065,-1.905) G31(-13.335,-1.905) G32(-14.605,-1.905) G33(-15.875,-1.905) G34(-17.145,-1.905) G35(-18.415,-1.905) G36(-19.685,-1.905) G37(-20.955,-1.905) G38(-22.225,-1.905) G39(-23.495,-1.905) G40(-24.765,-1.905) H1(24.765,-3.175) H2(23.495,-3.175) H3(22.225,-3.175) H4(20.955,-3.175) H5(19.685,-3.175) H6(18.415,-3.175) H7(17.145,-3.175) H8(15.875,-3.175) H9(14.605,-3.175) H10(13.335,-3.175) H11(12.065,-3.175) H12(10.795,-3.175) H13(9.525,-3.175) H14(8.255,-3.175) H15(6.985,-3.175) H16(5.715,-3.175) H17(4.445,-3.175) H18(3.175,-3.175) H19(1.905,-3.175) H20(0.635,-3.175) H21(-0.635,-3.175) H22(-1.905,-3.175) H23(-3.175,-3.175) H24(-4.445,-3.175) H25(-5.715,-3.175) H26(-6.985,-3.175) H27(-8.255,-3.175) H28(-9.525,-3.175) H29(-10.795,-3.175) H30(-12.065,-3.175) H31(-13.335,-3.175) H32(-14.605,-3.175) H33(-15.875,-3.175) H34(-17.145,-3.175) H35(-18.415,-3.175) H36(-19.685,-3.175) H37(-20.955,-3.175) H38(-22.225,-3.175) H39(-23.495,-3.175) H40(-24.765,-3.175) J1(24.765,-4.445) J2(23.495,-4.445) J3(22.225,-4.445) J4(20.955,-4.445) J5(19.685,-4.445) J6(18.415,-4.445) J7(17.145,-4.445) J8(15.875,-4.445) J9(14.605,-4.445) J10(13.335,-4.445) J11(12.065,-4.445) J12(10.795,-4.445) J13(9.525,-4.445) J14(8.255,-4.445) J15(6.985,-4.445) J16(5.715,-4.445) J17(4.445,-4.445) J18(3.175,-4.445) J19(1.905,-4.445) J20(0.635,-4.445) J21(-0.635,-4.445) J22(-1.905,-4.445) J23(-3.175,-4.445) J24(-4.445,-4.445) J25(-5.715,-4.445) J26(-6.985,-4.445) J27(-8.255,-4.445) J28(-9.525,-4.445) J29(-10.795,-4.445) J30(-12.065,-4.445) J31(-13.335,-4.445) J32(-14.605,-4.445) J33(-15.875,-4.445) J34(-17.145,-4.445) J35(-18.415,-4.445) J36(-19.685,-4.445) J37(-20.955,-4.445) J38(-22.225,-4.445) J39(-23.495,-4.445) J40(-24.765,-4.445) K1(24.765,-5.715) K2(23.495,-5.715) K3(22.225,-5.715) K4(20.955,-5.715) K5(19.685,-5.715) K6(18.415,-5.715) K7(17.145,-5.715) K8(15.875,-5.715) K9(14.605,-5.715) K10(13.335,-5.715) K11(12.065,-5.715) K12(10.795,-5.715) K13(9.525,-5.715) K14(8.255,-5.715) K15(6.985,-5.715) K16(5.715,-5.715) K17(4.445,-5.715) K18(3.175,-5.715) K19(1.905,-5.715) K20(0.635,-5.715) K21(-0.635,-5.715) K22(-1.905,-5.715) K23(-3.175,-5.715) K24(-4.445,-5.715) K25(-5.715,-5.715) K26(-6.985,-5.715) K27(-8.255,-5.715) K28(-9.525,-5.715) K29(-10.795,-5.715) K30(-12.065,-5.715) K31(-13.335,-5.715) K32(-14.605,-5.715) K33(-15.875,-5.715) K34(-17.145,-5.715) K35(-18.415,-5.715) K36(-19.685,-5.715) K37(-20.955,-5.715) K38(-22.225,-5.715) K39(-23.495,-5.715) K40(-24.765,-5.715)
DBV5
  rect 1.4x0.5 smd: 1(-1.1,0.95) 2(-1.1,0) 3(-1.1,-0.95) 4(1.1,-0.95) 5(1.1,0.95)
HDR_THVT_1X2_100_M
  rect 1.473x1.473 hole 0.965: 1(0,0)
  round 1.473 hole 0.965: 2(0,-2.54)
HDR_THVT_1X3_100_M
  rect 1.473x1.473 hole 0.965: 1(0,0)
  round 1.473 hole 0.965: 2(0,-2.54) 3(0,-5.08)
HEATSINK_270X270
  rect 6.858x6.858 smd: 1(0,0)
IND_SM_XFL4015
  rect 1.2x3.5 smd: 1(-1.225,0) 2(1.225,0)
LED_1206
  rect 1.27x1.6 smd: 1(-1.524,0) 2(1.524,0)
MFG125_PLATED
  round 3.556 hole 3.175: 1(0,0)
PDFN_6_P35MM
  custom 0.045x0.045 smd: 1(-0.5,0.35) 2(-0.5,0) 3(-0.5,-0.35) 4(0.5,-0.35) 5(0.5,0) 6(0.5,0.35)
QFN20_RGW_P65PITCH
  custom 0.09x0.09 smd: 1(-2.607,1.3) 2(-2.607,0.65) 3(-2.607,0) 4(-2.607,-0.65) 5(-2.607,-1.3) 6(-1.3,-2.607) 7(-0.65,-2.607) 8(0,-2.607) 9(0.65,-2.607) 10(1.3,-2.607) 11(2.607,-1.3) 12(2.607,-0.65) 13(2.607,0) 14(2.607,0.65) 15(2.607,1.3) 16(1.3,2.607) 17(0.65,2.607) 18(0,2.607) 19(-0.65,2.607) 20(-1.3,2.607)
  rect 3.302x3.302 smd: 21(0,0)
QFN40_RTA_RTB_RHA
  custom 0.076x0.076 smd: 1(-3.025,2.25) 2(-3.025,1.75) 3(-3.025,1.25) 4(-3.025,0.75) 5(-3.025,0.25) 6(-3.025,-0.25) 7(-3.025,-0.75) 8(-3.025,-1.25) 9(-3.025,-1.75) 10(-3.025,-2.25) 11(-2.25,-3.025) 12(-1.75,-3.025) 13(-1.25,-3.025) 14(-0.75,-3.025) 15(-0.25,-3.025) 16(0.25,-3.025) 17(0.75,-3.025) 18(1.25,-3.025) 19(1.75,-3.025) 20(2.25,-3.025) 21(3.025,-2.25) 22(3.025,-1.75) 23(3.025,-1.25) 24(3.025,-0.75) 25(3.025,-0.25) 26(3.025,0.25) 27(3.025,0.75) 28(3.025,1.25) 29(3.025,1.75) 30(3.025,2.25) 31(2.25,3.025) 32(1.75,3.025) 33(1.25,3.025) 34(0.75,3.025) 35(0.25,3.025) 36(-0.25,3.025) 37(-0.75,3.025) 38(-1.25,3.025) 39(-1.75,3.025) 40(-2.25,3.025)
  rect 4.572x4.572 smd: 41(0,0)
QFN_20_199X199_0P65MM
  rect 0.991x0.356 smd: 1(-2.4,1.3) 2(-2.4,0.65) 3(-2.4,0) 4(-2.4,-0.65) 5(-2.4,-1.3) 11(2.4,-1.3) 12(2.4,-0.65) 13(2.4,0) 14(2.4,0.65) 15(2.4,1.3)
  rect 0.356x0.991 smd: 6(-1.3,-2.4) 7(-0.65,-2.4) 8(0,-2.4) 9(0.65,-2.4) 10(1.3,-2.4) 16(1.3,2.4) 17(0.65,2.4) 18(0,2.4) 19(-0.65,2.4) 20(-1.3,2.4)
  rect 3.15x3.15 smd: 21(0,0)
QFN_64_360X360_0P50MM_PWRPAD
  oval 1.016x0.305 smd: 1(-4.58,3.753) 2(-4.58,3.252) 3(-4.58,2.752) 4(-4.58,2.252) 5(-4.58,1.751) 6(-4.58,1.251) 7(-4.58,0.751) 8(-4.58,0.25) 9(-4.58,-0.25) 10(-4.58,-0.751) 11(-4.58,-1.251) 12(-4.58,-1.751) 13(-4.58,-2.252) 14(-4.58,-2.752) 15(-4.58,-3.252) 16(-4.58,-3.753) 33(4.58,-3.753) 34(4.58,-3.252) 35(4.58,-2.752) 36(4.58,-2.252) 37(4.58,-1.751) 38(4.58,-1.251) 39(4.58,-0.751) 40(4.58,-0.25) 41(4.58,0.25) 42(4.58,0.751) 43(4.58,1.251) 44(4.58,1.751) 45(4.58,2.252) 46(4.58,2.752) 47(4.58,3.252) 48(4.58,3.753)
  oval 0.305x1.016 smd: 17(-3.753,-4.58) 18(-3.252,-4.58) 19(-2.752,-4.58) 20(-2.252,-4.58) 21(-1.751,-4.58) 22(-1.251,-4.58) 23(-0.751,-4.58) 24(-0.25,-4.58) 25(0.25,-4.58) 26(0.751,-4.58) 27(1.251,-4.58) 28(1.751,-4.58) 29(2.252,-4.58) 30(2.752,-4.58) 31(3.252,-4.58) 32(3.753,-4.58) 49(3.753,4.58) 50(3.252,4.58) 51(2.752,4.58) 52(2.252,4.58) 53(1.751,4.58) 54(1.251,4.58) 55(0.751,4.58) 56(0.25,4.58) 57(-0.25,4.58) 58(-0.751,4.58) 59(-1.251,4.58) 60(-1.751,4.58) 61(-2.252,4.58) 62(-2.752,4.58) 63(-3.252,4.58) 64(-3.753,4.58)
  rect 7.366x7.366 smd: 65(0,0)
QFN_72_10MMX10MM_0P50MM_PWRPAD
  oval 0.6x0.24 smd: 1(-4.9,4.25) 2(-4.9,3.75) 3(-4.9,3.25) 4(-4.9,2.75) 5(-4.9,2.25) 6(-4.9,1.75) 7(-4.9,1.25) 8(-4.9,0.75) 9(-4.9,0.25) 10(-4.9,-0.25) 11(-4.9,-0.75) 12(-4.9,-1.25) 13(-4.9,-1.75) 14(-4.9,-2.25) 15(-4.9,-2.75) 16(-4.9,-3.25) 17(-4.9,-3.75) 18(-4.9,-4.25) 37(4.9,-4.25) 38(4.9,-3.75) 39(4.9,-3.25) 40(4.9,-2.75) 41(4.9,-2.25) 42(4.9,-1.75) 43(4.9,-1.25) 44(4.9,-0.75) 45(4.9,-0.25) 46(4.9,0.25) 47(4.9,0.75) 48(4.9,1.25) 49(4.9,1.75) 50(4.9,2.25) 51(4.9,2.75) 52(4.9,3.25) 53(4.9,3.75) 54(4.9,4.25)
  oval 0.24x0.6 smd: 19(-4.25,-4.9) 20(-3.75,-4.9) 21(-3.25,-4.9) 22(-2.75,-4.9) 23(-2.25,-4.9) 24(-1.75,-4.9) 25(-1.25,-4.9) 26(-0.75,-4.9) 27(-0.25,-4.9) 28(0.25,-4.9) 29(0.75,-4.9) 30(1.25,-4.9) 31(1.75,-4.9) 32(2.25,-4.9) 33(2.75,-4.9) 34(3.25,-4.9) 35(3.75,-4.9) 36(4.25,-4.9) 55(4.25,4.9) 56(3.75,4.9) 57(3.25,4.9) 58(2.75,4.9) 59(2.25,4.9) 60(1.75,4.9) 61(1.25,4.9) 62(0.75,4.9) 63(0.25,4.9) 64(-0.25,4.9) 65(-0.75,4.9) 66(-1.25,4.9) 67(-1.75,4.9) 68(-2.25,4.9) 69(-2.75,4.9) 70(-3.25,4.9) 71(-3.75,4.9) 72(-4.25,4.9)
  rect 8.382x8.382 smd: 73(0,0)
QFN_RLT_7
  rect 1.016x0.305 smd: 1(-1.06,0.75) 2(-1.06,0.25) 3(-1.06,-0.25) 4(-1.06,-0.75)
  rect 1.829x0.356 smd: 5(0.66,-0.6) 6(0.66,0) 7(0.66,0.6)
SMA_SMEL_DUAL_PSF-S01_250X215
  rect 0.508x4.064 smd: 1(0,-2.032)
  rect 3.048x4.064 smd: 2(-3.556,-2.032) 3(3.556,-2.032) 4(-3.556,-2.032) 5(3.556,-2.032)
SMA_THVT_312X312
  round 2.337 hole 1.575: 1(0,0)
  round 2.464 hole 1.702: 2(-2.54,2.54) 3(2.54,2.54) 4(2.54,-2.54) 5(-2.54,-2.54)
SMD_JUMPER_L_0402
  rect 0.508x0.508 smd: 1(-0.508,0) 2(0.508,0) 3(0.508,1.016)
SMP_B120
  rect 0.508x1.321 smd: 1(0,-3.1)
  custom 1.3x1.3 smd: 2(0,0)
SON_Q5B_8
  rect 1.372x0.711 smd: 1(-2.767,1.905) 2(-2.767,0.635) 3(-2.767,-0.635) 4(-2.767,-1.905) 5(2.767,-1.905) 6(2.767,-0.635) 7(2.767,0.635) 8(2.767,1.905)
SSOP_28_413X220_26
  rect 1.778x0.406 smd: 1(-3.625,4.225) 2(-3.625,3.575) 3(-3.625,2.925) 4(-3.625,2.275) 5(-3.625,1.625) 6(-3.625,0.975) 7(-3.625,0.325) 8(-3.625,-0.325) 9(-3.625,-0.975) 10(-3.625,-1.625) 11(-3.625,-2.275) 12(-3.625,-2.925) 13(-3.625,-3.575) 14(-3.625,-4.225) 15(3.625,-4.225) 16(3.625,-3.575) 17(3.625,-2.925) 18(3.625,-2.275) 19(3.625,-1.625) 20(3.625,-0.975) 21(3.625,-0.325) 22(3.625,0.325) 23(3.625,0.975) 24(3.625,1.625) 25(3.625,2.275) 26(3.625,2.925) 27(3.625,3.575) 28(3.625,4.225)
SW_SMVT_SPST_EVQPJX_2
  rect 2.007x1.6 smd: 1(-2.7,0) 2(2.7,0)
TANT_B
  rect 1.6x2.413 smd: 1(-1.867,0) 2(1.867,0)
TESTPOINT_62DIA
  round 2.337 hole 1.575: 1(0,0)
TFMR_5_150X150_50
  rect 1.651x0.762 smd: 1(1.587,1.27) 2(1.587,0) 3(1.587,-1.27) 4(-1.587,-1.27) 6(-1.587,1.27)
TP_THVT_060_RND
  round 1.575 hole 1.016: 1(0,0)
TSSOP14
  rect 1.651x0.33 smd: 1(-2.87,1.956) 2(-2.87,1.306) 3(-2.87,0.655) 4(-2.87,0.005) 5(-2.87,-0.645) 6(-2.87,-1.295) 7(-2.87,-1.946) 8(2.87,-1.946) 9(2.87,-1.295) 10(2.87,-0.645) 11(2.87,0.005) 12(2.87,0.655) 13(2.87,1.306) 14(2.87,1.956)
VCXO_6_CUSTOM
  rect 5.74x1.956 smd: 1(-3.81,2.54) 2(-3.81,0) 3(-3.81,-2.54) 4(3.81,-2.54) 5(3.81,0) 6(3.81,2.54)

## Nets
1.4V: C122.1 C126.1 C376.1 L2.2 R153.1 R154.1 R157.2 SJP3.1(PIN1) TP28.1(TP) U11.4(VOS) U17.5(IN1) U17.6(IN2) U17.7(IN3) U17.8(IN4)
3.3VUSB: C105.1 C369.2 U5.4(VCCIO) U5.17(3V3OUT) U29.14(VCCB)
5.0V_IN: F1.1 J15.1 Q1.5(D5) Q1.6(D6) Q1.7(D7) Q1.8(D8) TP17.1(TP) U15.5(VIN)
5VIN: C121.1 C156.1 C172.1 C173.1 C183.1 C198.1 C203.1 C386.1 F1.2 Q1.1(S1) Q1.2(S2) Q1.3(S3) R95.1 R133.1 SJP4.1(PIN1) U11.1(EN) U11.7(IN) U12.13(EN) U12.15(IN2) U12.16(IN1) U14.1(EN) U14.7(IN) U17.10(BIAS) U18.7(IN) U31.13(EN) U31.15(IN2) U31.16(IN1)
+1.9V: FB20.3 SJP5.3(PIN3)
+2.2V: C184.1 C189.1 C190.1 C191.1 L1.2 R132.1 R136.1 SJP2.1(PIN1) TP26.1(TP) U14.4(VOS) U16.15(IN3) U16.16(IN2) U16.17(IN1)
+3.3V_LMX: C381.1 C382.1 C383.1 C384.1 C390.2 C392.1 C393.1 C396.1 C397.1 C398.2 C401.1 C402.2 FB22.2 R186.2 TP34.1(TP) U30.7(VCCDIG) U30.11(VCCCP) U30.15(VCCDIV) U30.21(VCCBUF) U30.26(VCCDBLR) U30.37(VCCVCO)
+3.3V_LMXRF: C379.1 C380.1 C408.1 C411.1 C428.1 FB21.2 R175.2 R176.2 R177.2 R178.2 R188.1 R189.1
+3.3VCLK: C160.1 C161.1 C162.1 C163.1 FB1.2 FB2.1 FB3.1 FB4.1 FB5.1 FB6.1 FB10.1 FB11.1 FB16.2 R71.1 R76.1 SJP1.3(PIN3) TP12.1(TP)
AVDD1.9V: C48.1 C49.1 C50.1 C51.1 C52.1 C53.1 C185.1 C186.1 C187.1 C188.1 FB20.1 R137.1 R166.1 R167.1 TP20.1(TP) U1.10(AVDD19#10) U1.16(AVDD19#16) U1.24(AVDD19#24) U1.31(AVDD19#31) U1.39(AVDD19#39) U1.45(AVDD19#45) U16.1(OUT1) U16.2(SNS) U16.19(OUT2) U16.20(OUT3)
AVDD1.15V: C37.1 C38.1 C39.1 C40.1 C41.1 C42.1 C43.1 C44.1 C45.1 C46.1 C47.1 C194.1 C195.1 C196.1 FB17.3 TP22.1(TP) U1.9(AVDD#9) U1.12(AVDD#12) U1.15(AVDD#15) U1.17(AVDD#17) U1.25(AVDD#25) U1.30(AVDD#30) U1.38(AVDD#38) U1.40(AVDD#40) U1.43(AVDD#43) U1.44(AVDD#44) U1.46(AVDD#46)
DVDD1.15V: C54.1 C55.1 C56.1 C57.1 C58.1 C59.1 C60.1 C377.1 C378.1 FB19.3 JP1.1(PIN1) R31.1 R33.1 R34.1 SJP5.1(PIN1) TP30.1(TP) U1.4(DVDD#4) U1.8(DVDD#8) U1.47(DVDD#47) U1.51(DVDD#51) U1.57(DVDD#57) U1.64(DVDD#64) U1.70(DVDD#70)
GND: C33.2 C37.2 C38.2 C39.2 C40.2 C41.2 C42.2 C43.2 C44.2 C45.2 C46.2 C47.2 C48.2 C49.2 C50.2 C51.2 C52.2 C53.2 C54.2 C55.2 C56.2 C57.2 C58.2 C59.2 C60.2 C61.2 C68.2 C72.2 C75.1 C77.1 C78.1 C79.1 C80.1 C83.1 C86.1 C87.1 C88.1 C89.1 C90.1 C91.1 C92.1 C93.1 C94.1 C95.1 C96.2 C97.2 C98.1 C99.1 C101.2 C102.2 C103.2 C104.2 C105.2 C121.2 C122.2 C126.2 C156.2 C157.2 C158.2 C159.2 C160.2 C161.2 C162.2 C163.2 C166.2 C172.2 C173.2 C183.2 C184.2 C185.2 C186.2 C187.2 C188.2 C189.2 C190.2 C191.2 C194.2 C195.2 C196.2 C197.2 C198.2 C203.2 C204.2 C368.2 C369.1 C376.2 C377.2 C378.2 C379.2 C380.2 C381.2 C382.2 C383.2 C384.2 C385.2 C386.2 C387.2 C388.2 C389.2 C390.1 C391.1 C392.2 C393.2 C395.2 C396.2 C397.2 C398.1 C399.2 C400.1 C401.2 C402.1 C403.1 C404.1 C405.1 C406.1 C407.1 C408.2 C411.2 C420.2 C421.2 C424.1 C425.1 C426.1 C427.1 C428.2 D1.2(CATHODE) D2.2(CATHODE) D3.2(CATHODE) D4.2(CATHODE) D5.2(CATHODE) D6.2(CATHODE) D7.2(CATHODE) FB17.2 FB19.2 FB20.2 HS1.1 J1.2(SHIELD2) J1.3(SHIELD3) J1.4(SHIELD4) J1.5(SHIELD1) J2.2(SHIELD2) J2.3(SHIELD3) J2.4(SHIELD4) J2.5(SHIELD1) J3.2(SHIELD2) J3.3(SHIELD3) J3.4(SHIELD4) J3.5(SHIELD1) J4.2(SHIELD2) J4.3(SHIELD3) J4.4(SHIELD4) J4.5(SHIELD1) J5.2(SHIELD2) J5.3(SHIELD3) J5.4(SHIELD4) J5.5(SHIELD1) J7.2(GND#2) J7.3(GND#3) J7.4(GND#4) J7.5(GND#5) J10.A1 J10.A4 J10.A5 J10.A8 J10.A9 J10.A12 J10.A13 J10.A16 J10.A17 J10.A20 J10.A21 J10.A24 J10.A25 J10.A28 J10.A29 J10.A32 J10.A33 J10.A36 J10.A37 J10.A40 J10.B2 J10.B3 J10.B6 J10.B7 J10.B10 J10.B11 J10.B14 J10.B15 J10.B18 J10.B19 J10.B22 J10.B23 J10.B26 J10.B27 J10.B30 J10.B31 J10.B34 J10.B35 J10.B38 J10.B39 J10.C1 J10.C4 J10.C5 J10.C8 J10.C9 J10.C12 J10.C13 J10.C16 J10.C17 J10.C20 J10.C21 J10.C24 J10.C25 J10.C28 J10.C29 J10.C32 J10.C33 J10.C36 J10.C38 J10.C40 J10.D2 J10.D3 J10.D6 J10.D7 J10.D10 J10.D13 J10.D16 J10.D19 J10.D22 J10.D25 J10.D28 J10.D37 J10.D39 J10.E1 J10.E4 J10.E5 J10.E8 J10.E11 J10.E14 J10.E17 J10.E20 J10.E23 J10.E26 J10.E29 J10.E32 J10.E35 J10.E38 J10.E40 J10.F2 J10.F3 J10.F6 J10.F9 J10.F12 J10.F15 J10.F18 J10.F21 J10.F24 J10.F27 J10.F30 J10.F33 J10.F36 J10.F39 J10.G1 J10.G4 J10.G5 J10.G8 J10.G11 J10.G14 J10.G17 J10.G20 J10.G23 J10.G26 J10.G29 J10.G32 J10.G35 J10.G38 J10.G40 J10.H3 J10.H6 J10.H9 J10.H12 J10.H15 J10.H18 J10.H21 J10.H24 J10.H27 J10.H30 J10.H33 J10.H36 J10.H39 J10.J1 J10.J4 J10.J5 J10.J8 J10.J11 J10.J14 J10.J17 J10.J20 J10.J23 J10.J26 J10.J29 J10.J32 J10.J35 J10.J38 J10.J40 J10.K2 J10.K3 J10.K6 J10.K9 J10.K12 J10.K15 J10.K18 J10.K21 J10.K24 J10.K27 J10.K30 J10.K33 J10.K36 J10.K39 J11.5(GND) J11.6(GND1) J11.7(GND2) J11.8(GND3) J11.9(GND4) J13.2(GND#2) J13.3(GND#3) J13.4(GND#4) J13.5(GND#5) J14.2(GND#2) J14.3(GND#3) J14.4(GND#4) J14.5(GND#5) J15.2 J15.3 J16.2(SHIELD1) JP1.3(PIN3) JP2.1 JP3.2(PIN2) MT1.1 MT2.1 R32.2 R35.2 R47.2 R50.2 R51.2 R52.2 R53.2 R54.2 R55.2 R58.2 R59.2 R63.2 R64.2 R67.2 R68.2 R69.2 R70.2 R73.2 R74.2 R77.2 R78.2 R81.2 R82.2 R89.2 R96.1 R124.1 R125.1 R126.1 R127.1 R134.2 R138.1 R139.1 R140.1 R141.1 R145.2 R147.2 R151.2 R152.2 R155.2 R168.2 R169.2 R170.1 R171.1 R172.1 R173.1 R174.2 R179.1 R180.2 R181.2 R187.1 R192.1 SJP1.1(PIN1) SJP2.3(PIN3) SJP3.3(PIN3) SJP4.3(PIN3) T5.6(PRI DOT) T6.2(SECONDARY_CT) T6.4(PRIMARY) TP18.1(TP) TP19.1(TP) TP21.1(TP) TP27.1(TP) TP29.1(TP) TP31.1(TP) U1.3(DGND#3) U1.18(AGND#18) U1.23(AGND#23) U1.26(AGND#26) U1.29(AGND#29) U1.32(AGND#32) U1.37(AGND#37) U1.52(DGND#52) U1.60(DGND#60) U1.67(DGND#67) U1.73(THERMALPAD) U3.65(DAP) U5.7(GND#7) U5.18(GND#18) U5.21(GND#21) U5.25(AGND) U5.26(TEST) U11.5(GND) U12.7(GND) U12.21(PWRPAD) U14.5(GND) U15.2(GND) U16.8(GND1) U16.18(GND2) U16.21(PWRPAD) U17.12(GND) U17.21(PWRPAD) U18.5(GND) U29.7(GND) U30.2(GND#2) U30.4(GND#4) U30.6(GND#6) U30.13(GND#13) U30.14(GND#14) U30.25(GND#25) U30.31(GND#31) U30.34(GND#34) U30.39(GND#39) U30.40(NC4) U30.41(PWRPAD) U31.7(GND) U31.21(PWRPAD) U32.2(GND) U33.2(GND) Y1.3(GND)
V1: JP3.1(PIN1) R188.2 U32.1(V1) U33.1(V1)
V2: JP3.3(PIN3) R189.2 U32.5(V2) U33.5(V2)
A_IN_M: C415.1 J2.1(CENTER)
A_IN_P: C414.1 J1.1(CENTER)
ADC_CLK: C28.1 J5.1(CENTER)
ADC_CLKM: C430.2 R26.1 U1.28(CLKINM)
ADC_CLKP: C429.2 R26.2 U1.27(CLKINP)
ADC_SCLK: U1.6(SCLK) U29.2(A1)
ADC_SDIO: U1.5(SDATA) U29.3(A2)
ADC_SDO: U1.11(SDOUT) U29.4(A3)
ADC_SEN: R34.2 U1.7(SEN) U29.5(A4)
AIN+: C1.1 R1.2 T1.1(SEC DOT) T2.3(SEC)
AIN-: C6.1 R11.2 T1.3(SEC) T2.1(SEC DOT)
AINM: C1.2 T2.4(PRI) U1.41(INAM)
AINP: C6.2 T2.6(PRI DOT) U1.42(INAP)
B_IN_M: C417.1 J4.1(CENTER)
B_IN_P: C416.1 J3.1(CENTER)
BIN+: C12.1 R23.2 T3.3(SEC) T4.1(SEC DOT)
BIN-: C7.1 R13.2 T3.1(SEC DOT) T4.3(SEC)
BINM: C12.2 T4.6(PRI DOT) U1.14(INBM)
BINP: C7.2 T4.4(PRI) U1.13(INBP)
CE: JP2.2 R186.1 U30.1(CE)
CLK-IN: R56.1 R57.2 R59.1 R191.1 T6.6(PRIMARY_DOT)
CLK_LAO_0M: J10.G7 R79.2
CLK_LAO_0P: J10.G6 R75.2
CLKIN1_N: C74.2 C75.2 U3.35(CLKIN1N/FBCLKINN/FINN)
CLKIN1_P: C73.2 U3.34(CLKIN1P/FBCLKINP/FINP)
CLKINN: C74.1 R60.2 T6.3(SECONDARY)
CLKINP: C73.1 R55.1 R56.2 R60.1 T6.1(SECONDARY_DOT)
CLKLA_0M: R78.1 R79.1 U3.63(DCLKOUT12N)
CLKLA_0P: R75.1 R77.1 U3.62(DCLKOUT12P)
CLKM: C9.2 C432.2
CLKP: C8.2 C431.2
CP1: C68.1 C70.1 U3.32(CPOUT1) Y1.1(VC)
CP2: C71.1 C72.1 U3.46(CPOUT2)
CPOUT: C394.1 C395.1 R182.1 U30.12(CPOUT)
DA0_M: C14.1 U1.62(DA0M)
DA0_P: C13.1 U1.61(DA0P)
DA0M: C14.2 J10.B13
DA0P: C13.2 J10.B12
DA1_M: C16.1 U1.59(DA1M)
DA1_P: C15.1 U1.58(DA1P)
DA1M: C16.2 J10.A15
DA1P: C15.2 J10.A14
DA2_M: C18.1 U1.56(DA2M)
DA2_P: C17.1 U1.55(DA2P)
DA2M: C18.2 J10.B17
DA2P: C17.2 J10.B16
DA3_M: C20.1 U1.54(DA3M)
DA3_P: C19.1 U1.53(DA3P)
DA3M: C20.2 J10.A19
DA3P: C19.2 J10.A18
DB0_M: C22.1 U1.65(DB0M)
DB0_P: C21.1 U1.66(DB0P)
DB0M: C22.2 J10.A11
DB0P: C21.2 J10.A10
DB1_M: C24.1 U1.68(DB1M)
DB1_P: C23.1 U1.69(DB1P)
DB1M: C24.2 J10.C7
DB1P: C23.2 J10.C6
DB2_M: C27.1 U1.71(DB2M)
DB2_P: C26.1 U1.72(DB2P)
DB2M: C27.2 J10.A7
DB2P: C26.2 J10.A6
DB3_M: C31.1 U1.1(DB3M)
DB3_P: C30.1 U1.2(DB3P)
DB3M: C31.2 J10.A3
DB3P: C30.2 J10.A2
DCLKOUT10N: C171.1 R151.1 U3.55(DCLKOUT10N)
DCLKOUT10P: C170.1 R152.1 U3.54(DCLKOUT10P)
FMC_CTRL1: J10.C26 R165.1
FMC_CTRL2: J10.C27 R164.1
FPGA_JESD_CLKM: C69.2 J10.D5
FPGA_JESD_CLKP: C67.2 J10.D4
FPGA_JESD_SYSREFM: J10.G10 R49.2
FPGA_JESD_SYSREFP: J10.G9 R48.2
GPIO1: TP3.1(TP) U1.19(GPIO1)
GPIO2: TP7.1(TP) U1.63(GPIO2)
GTXCLKM: C69.1 R52.1 U3.2(DCLKOUT0N)
GTXCLKP: C67.1 R53.1 U3.1(DCLKOUT0P)
JESD_SYSREFM: R49.1 R50.1 U3.4(SDCLKOUT1N)
JESD_SYSREFP: R48.1 R51.1 U3.3(SDCLKOUT1P)
LMK LOCKED: D3.1(ANODE) R86.1
LMK_CLKIN: J7.1(CENTER) R57.1 R58.1
LMK_CSB: U3.18(\\C\S\) U5.6(D7)
LMK_SCLK: U3.19(SCK) U5.1(D0) U29.13(B1) U30.16(SCK)
LMK_SDIO: U3.20(SDIO) U5.5(D1) U29.12(B2) U30.17(SDI)
LMK_SDO: U3.5(RESET) U5.10(D6)
LMX_CLKB: C412.2 R191.2 R192.2
LMX_CLKM: C410.2 C432.1 U32.3(RF1)
LMX_CLKP: C409.2 C431.1 U33.3(RF1)
LMX_CSB: U5.9(D5) U30.24(CSB)
LMX_OSCM: C418.2 U30.9(OSCINM)
LMX_OSCP: C419.2 U30.8(OSCINP)
LMX_SDO: R184.2 U5.2(D4)
OSCINN: C85.2 C86.2 U3.44(OSCINN)
OSCINP: C82.2 C83.2 U3.43(OSCINP)
OSCN: C84.2 C85.1 R76.2 R82.1
OSCOUTN: C419.1 R180.1 U3.41(OSCOUTN)
OSCOUTP: C418.1 R181.1 U3.40(OSCOUTP)
OSCP: C81.2 C82.1 R71.2 R74.1
PDN: JP1.2(PIN2) U1.50(PDN)
PLL2 LOCKED: D4.1(ANODE) R87.1
RESET: R35.1 SW1.2 U1.48(RESET)
RFOUTBM: C413.2 J16.1(CENTER) R187.2
SCAN_EN: R31.2 R32.1 U1.49(SCAN_EN)
STAT 0: D1.1(ANODE) R84.1
STAT 1: D2.1(ANODE) R85.1
SYNC: TP25.1(TP) U3.6(SYNC)
SYNCBM: J10.G13 R166.2 R168.1 U1.36(SYNCBM)
SYNCBP: J10.G12 R167.2 R169.1 U1.35(SYNCBP)
SYSREF+: R65.1 R67.1 U3.13(SDCLKOUT3P)
SYSREF-: R66.1 R68.1 U3.14(SDCLKOUT3N)
SYSREFM: R29.1 R66.2 R69.1 U1.34(SYSREFM)
SYSREFP: R29.2 R65.2 R70.1 U1.33(SYSREFP)
U17_BYPASS: R157.1 R159.2
VCM: C61.1 TP2.1(TP) U1.22(VCM)
Y2_N: R80.1 R81.1 Y1.4(OUT_N)
Y2_P: R72.1 R73.1 Y1.5(OUT_P)
YO2_N: C84.1 R80.2
YO2_P: C81.1 R72.2
N851442: C414.2 C424.2 R1.1 T1.6(PRI DOT)
N16260551: C416.2 C426.2 R13.1 T3.6(PRI DOT)
N17912008: C415.2 C425.2 R11.1 T1.4(PRI)
N18340257: D6.1(ANODE) R133.2
N19112270: C417.2 C427.2 R23.1 T3.4(PRI)
N19631315: C157.1 C158.1 C159.1 FB16.1 U12.1(OUT1) U12.3(SENSE) U12.20(OUT2)
N19631466: C166.1 U12.14(NR)
N19631491: R127.2 U12.8(1P6V)
N19631493: R125.2 U12.11(0P2V)
N19631495: R124.2 U12.12(0P1V)
N19631505: R126.2 U12.10(0P4V)
N19879103: C104.1 J11.3(D+) U5.15(USBDP)
N19879131: J11.4(ID) R96.2
N19879145: FB12.2 J11.1(VBUS)
N19879149: C103.1 J11.2(D-) U5.16(USBDM)
N19879167: C101.1 C102.1 FB12.1 R95.2 TP4.1(TP) U5.20(VCC)
N19879302: U5.11(D3) U29.10(B4)
N19879304: U5.3(D2) U29.11(B3)
N19881704: J10.C18 R88.2
N19881714: J10.H2 R89.1
N19881723: D5.1(ANODE) R88.1
N19884870: C77.2 C78.2 C79.2 C80.2 FB1.1 Y1.6(VDD)
N19884947: SJP1.2(PIN2) Y1.2(NC)
N19886018: C9.1 R64.1 U3.16(DCLKOUT2N)
N19886020: C8.1 R63.1 U3.15(DCLKOUT2P)
N19887754: FB8.2 U3.42(VCC8_OSCIN)
N19887756: C93.2 C94.2 C95.2 FB6.2 FB7.1 FB8.1 FB9.1 U3.47(VCC10_PLL2)
N19887760: C98.2 FB10.2 U3.53(VCC11_CG3)
N19887762: C99.2 FB11.2 U3.64(VCC12_CG0)
N19887789: R86.2 U3.31(STATUS_LD1)
N19887795: R87.2 U3.48(STATUS_LD2)
N19887804: R85.2 U3.59(CLKIN_SEL1)
N19887822: R84.2 U3.58(CLKIN_SEL0)
N19887828: C96.1 U3.12(LDOBYP2)
N19887830: C97.1 U3.11(LDOBYP1)
N19887836: C87.2 C88.2 C89.2 FB2.2 U3.10(VCC1_VCO) U3.33(VCC5_DIG) U3.36(VCC6_PLL1)
N19887876: FB7.2 U3.39(VCC7_OSCOUT)
N19887878: FB9.2 U3.45(VCC9_CP2)
N19887910: C91.2 FB4.2 U3.21(VCC3_SYSREF)
N19887912: C90.2 FB3.2 U3.17(VCC2_CG1)
N19887930: C92.2 FB5.2 U3.26(VCC4_CG2)
N19893167: C372.1 T5.3(SEC)
N19893194: C373.1 T5.1(SEC DOT)
N19893222: C28.2 T5.4(PRI)
N19893438: C33.1 T5.2(NC)
N19895463: C372.2 U32.4(RF2)
N19895477: C373.2 U33.4(RF2)
N19955835: Q1.4(G) U15.4(GATE)
N20015888: C170.2 J13.1(CENTER)
N20015984: C171.2 J14.1(CENTER)
N20042801: R139.2 U16.7(200MV)
N20043120: R138.2 U16.6(100MV)
N20043460: R140.2 U16.9(400MV)
N20043630: R141.2 U16.10(800MV)
N20048856: R137.2 U16.4(PG)
N20080651: C368.1 SJP5.2(PIN2) U29.1(VCCA) U29.8(OE)
N20101312: R132.2 R134.1 U14.3(FB)
N20101314: L1.1 U14.6(SW)
N20101373: R136.2 U14.2(PG)
N20111831: R154.2 R155.1 U11.3(FB)
N20111833: L2.1 U11.6(SW)
N20111884: R153.2 U11.2(PG)
N20113513: C193.1 C197.1 R143.1 R158.2 U17.1(OUT4) U17.18(OUT1) U17.19(OUT2) U17.20(OUT3)
N20113515: C193.2 R143.2 R145.1 U17.16(FB/SNS)
N20114896: C204.1 FB19.1 L3.2 R146.1 R148.1 U18.4(VOS)
N20114915: R146.2 R147.1 U18.3(FB)
N20114917: L3.1 U18.6(SW)
N20114968: R148.2 U18.2(PG)
N20121078: FB17.1 R158.1 R159.1
N20150497: SJP2.2(PIN2) U16.14(EN)
N20151052: SJP3.2(PIN2) U17.11(EN)
N20152729: SJP4.2(PIN2) U18.1(EN)
N20210385: R40.2 R165.2 TP32.1(TP) U1.20(CTRL1)
N20210389: R40.1 R164.2 TP33.1(TP) U1.21(CTRL2)
N20213760: R33.2 SW1.1
N20220794: C385.1 C388.1 C389.1 FB21.1 FB22.1 U31.1(OUT1) U31.3(SENSE) U31.20(OUT2)
N20220969: C387.1 U31.14(NR)
N20220990: R171.2 U31.8(1P6V)
N20220992: R172.2 U31.11(0P2V)
N20220994: R170.2 U31.12(0P1V)
N20221006: R173.2 U31.10(0P4V)
N20227487: C399.1 C400.2 U30.27(VBIASBANK)
N20231187: C403.2 U30.3(VBIASVCO)
N20232417: C404.2 U30.38(VREGVCO)
N20232915: C405.2 U30.29(VREFVCO#29)
N20233092: C406.2 U30.36(VREFVCO#36)
N20234062: C407.2 U30.33(VBIASVARAC)
N20235277: C409.1 R175.1 U30.23(RFOUTAP)
N20235286: C410.1 R176.1 U30.22(RFOUTAM)
N20237052: C412.1 R177.1 U30.18(RFOUTBP)
N20237066: C413.1 R178.1 U30.19(RFOUTBM)
N20239082: R179.2 U30.30(REXT)
N20249678: C391.2 U30.10(VCCIN)
N20251064: C394.2 R174.1
N20251377: C420.1 R182.2 R183.1
N20251505: C421.1 R183.2 U30.35(VTUNE)
N20257347: R184.1 R185.2 U30.20(MUXOUT)
N20258125: D7.1(ANODE) R185.1
N20306930: C429.1 U32.6(RFC)
N20306944: C430.1 U33.6(RFC)
N198851401: C71.2 R54.1
